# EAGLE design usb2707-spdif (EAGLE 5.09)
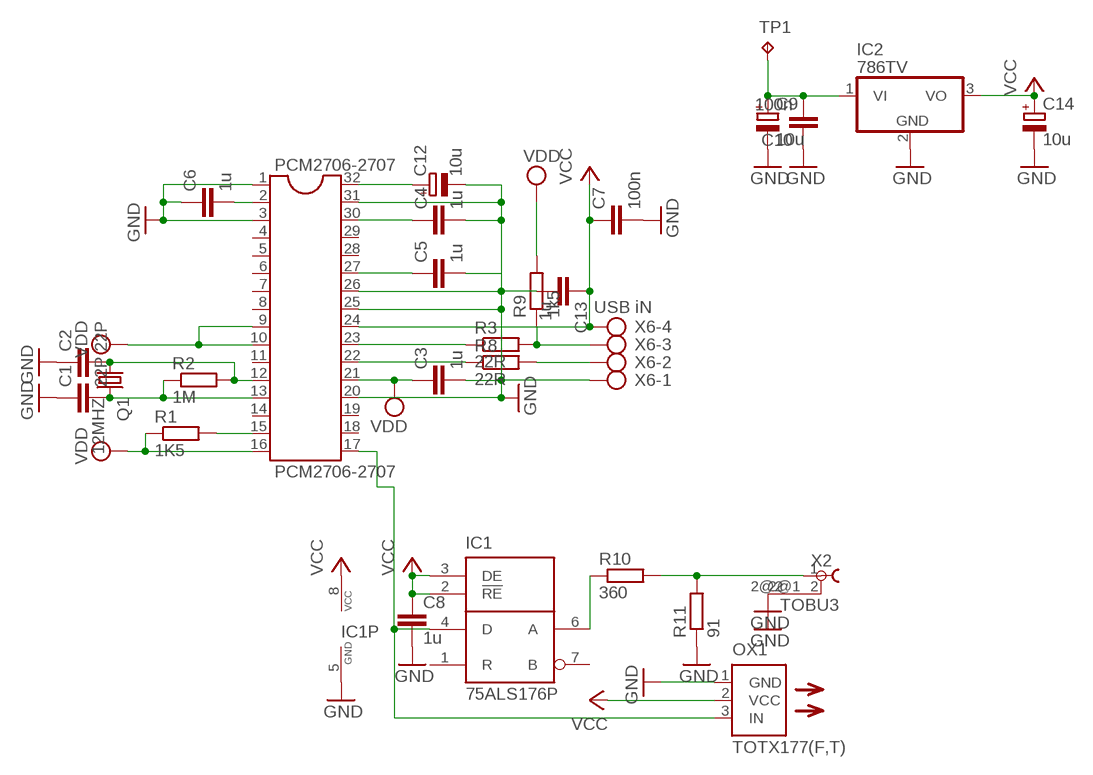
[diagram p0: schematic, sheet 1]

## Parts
C1  22P  C5/2.5  [C5B2.5]
C2  22P  C5/2.5  [C5B2.5]
C3  1u  C5/2.5  [C5B2.5]
C4  1u  C5/2.5  [C5B2.5]
C5  1u  C5/2.5  [C5B2.5]
C6  1u  C5/2.5  [C5B2.5]
C7  100n  C5/2.5  [C5B2.5]
C8  1u  C5/2.5  [C5B2.5]
C9  10u  CPOL-EUE5-5  [E5-5]
C10  100n  C5/2.5  [C5B2.5]
C12  10u  CPOL-EUE5-5  [E5-5]
C13  1u  C5/2.5  [C5B2.5]
C14  10u  CPOL-EUE5-5  [E5-5]
IC1  75ALS176P  [DIL08]
IC2  786TV  [TO220V]
OX1  TOTX177(F,T)  [TOTX]
PCM2706-2707  PCM2706-2707  DIL32  [DIL32]
Q1  12MHZ  CRYSTALHC49U-V  [HC49U-V]
R1  1K5  R-EU_0207/10  [0207/10]
R2  1M  R-EU_0207/10  [0207/10]
R3  22R  R-EU_0207/10  [0207/10]
R8  22R  R-EU_0207/10  [0207/10]
R9  1k5  R-EU_0207/10  [0207/10]
R10  360  R-EU_0207/10  [0207/10]
R11  91  R-EU_0207/10  [0207/10]
TP1  TPPAD1-13Y  [P1-13Y]
X2  TOBU3  [TOBU3]
X6  USB iN  AK500/4  [AK500/4]

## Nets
GND: C1.1 C2.1 C3.2 C4.2 C5.2 C6.1 C7.2 C8.2 C9.- C10.1 C12.- C13.2 C14.- IC1.5(GND) IC2.2(GND) OX1.1(GND) PCM2706-2707.1 PCM2706-2707.3 PCM2706-2707.20 PCM2706-2707.25 PCM2706-2707.26 PCM2706-2707.31 R11.1 X2.2@2 X6.1
N$1: C6.2 PCM2706-2707.2
N$2: C5.1 PCM2706-2707.27
N$3: C4.1 PCM2706-2707.30
N$4: C12.+ PCM2706-2707.32
N$5: R3.2 R9.1 X6.3
N$6: PCM2706-2707.15 R1.2
N$7: C9.+ C10.2 IC2.1(VI) TP1.TP
N$8: C2.2 PCM2706-2707.12 Q1.1 R2.2
N$9: C1.2 PCM2706-2707.13 Q1.2 R2.1
N$19: PCM2706-2707.23 R3.1
N$20: PCM2706-2707.22 R8.1
N$21: IC1.4(D) OX1.3(IN) PCM2706-2707.17
N$22: R8.2 X6.2
N$23: R10.2 R11.2 X2.1
N$30: IC1.6(A) R10.1
VCC: C7.1 C8.1 C13.1 C14.+ IC1.2(!RE) IC1.3(DE) IC1.8(VCC) IC2.3(VO) OX1.2(VCC) PCM2706-2707.24 X6.4
VDD: C3.1 PCM2706-2707.9 PCM2706-2707.10 PCM2706-2707.16 PCM2706-2707.21 R1.1 R9.2
Unconnected: IC1.1(R) IC1.7(B) PCM2706-2707.4 PCM2706-2707.5 PCM2706-2707.6 PCM2706-2707.7 PCM2706-2707.8 PCM2706-2707.11 PCM2706-2707.14 PCM2706-2707.18 PCM2706-2707.19 PCM2706-2707.28 PCM2706-2707.29 X2.2 X2.2@1

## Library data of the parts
C1-C8 C10 C13 = capacitor-wima:C: CAPACITOR
C9 C12 C14 = rcl:CPOL-EU: POLARIZED CAPACITOR, European symbol
IC1 = texas:75ALS176: DIFFERENTIAL BUS TRANSCEIVERS TIA/EIA-422-B, TIA/EIA-422-B + TIA/EIA-422-B TIA/EIA-422-B Operate at Data Rates up to 35 Mbaud Source: http://focus.ti.com/lit/ds/symlink/sn65als176.pdf
IC2 = linear:78*: Positive VOLTAGE REGULATOR Source: http://cache.national.com/ds/LM/LM78L05.pdf http://www.fairchildsemi.com/ds/LM/LM7805.pdf
OX1 = pavouk:TOTX177(F,T): FIBER OPTIC TRANSMITTING MODULE
PCM2706-2707 = ic-package:DIL32: Dual In Line
Q1 = crystal:CRYSTAL: CRYSTAL
R1-R3 R8-R11 = rcl:R-EU_: RESISTOR, European symbol
TP1 = testpad:TP: Test pad
X2 = con-hirschmann:TOBU3: Female Cinch CONNECTOR ( RCA Jack )
X6 = con-ptr500:AK500/4: CONNECTOR

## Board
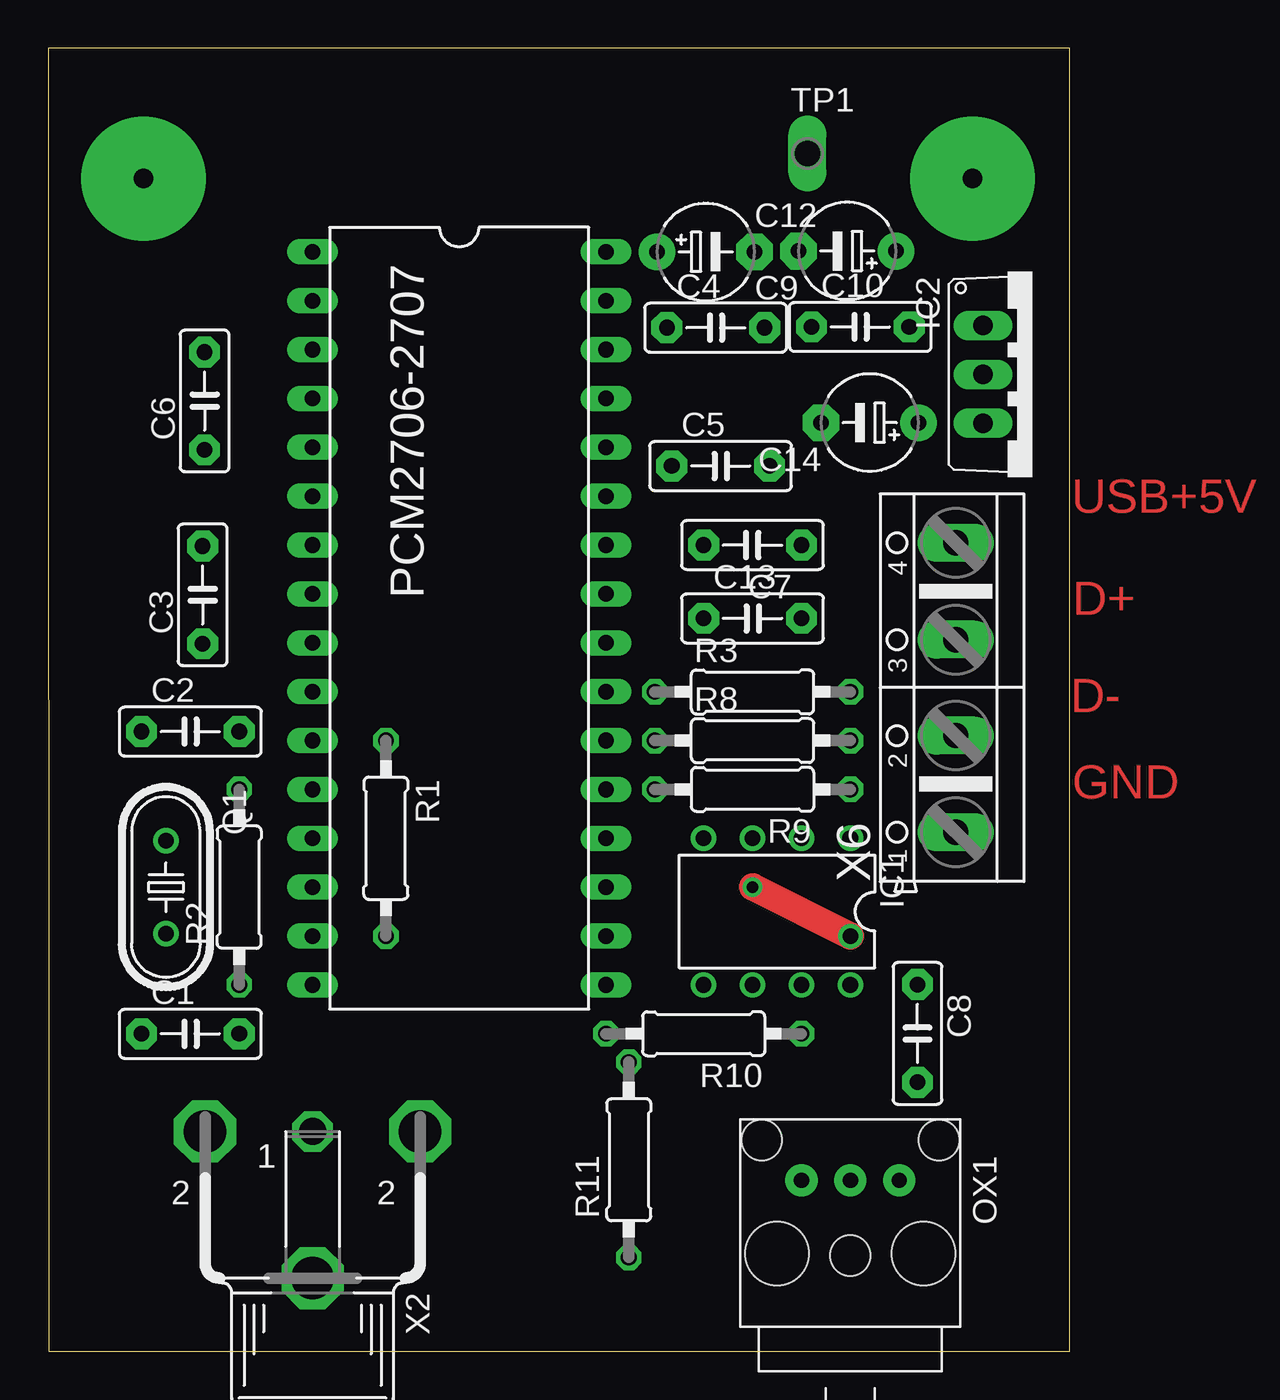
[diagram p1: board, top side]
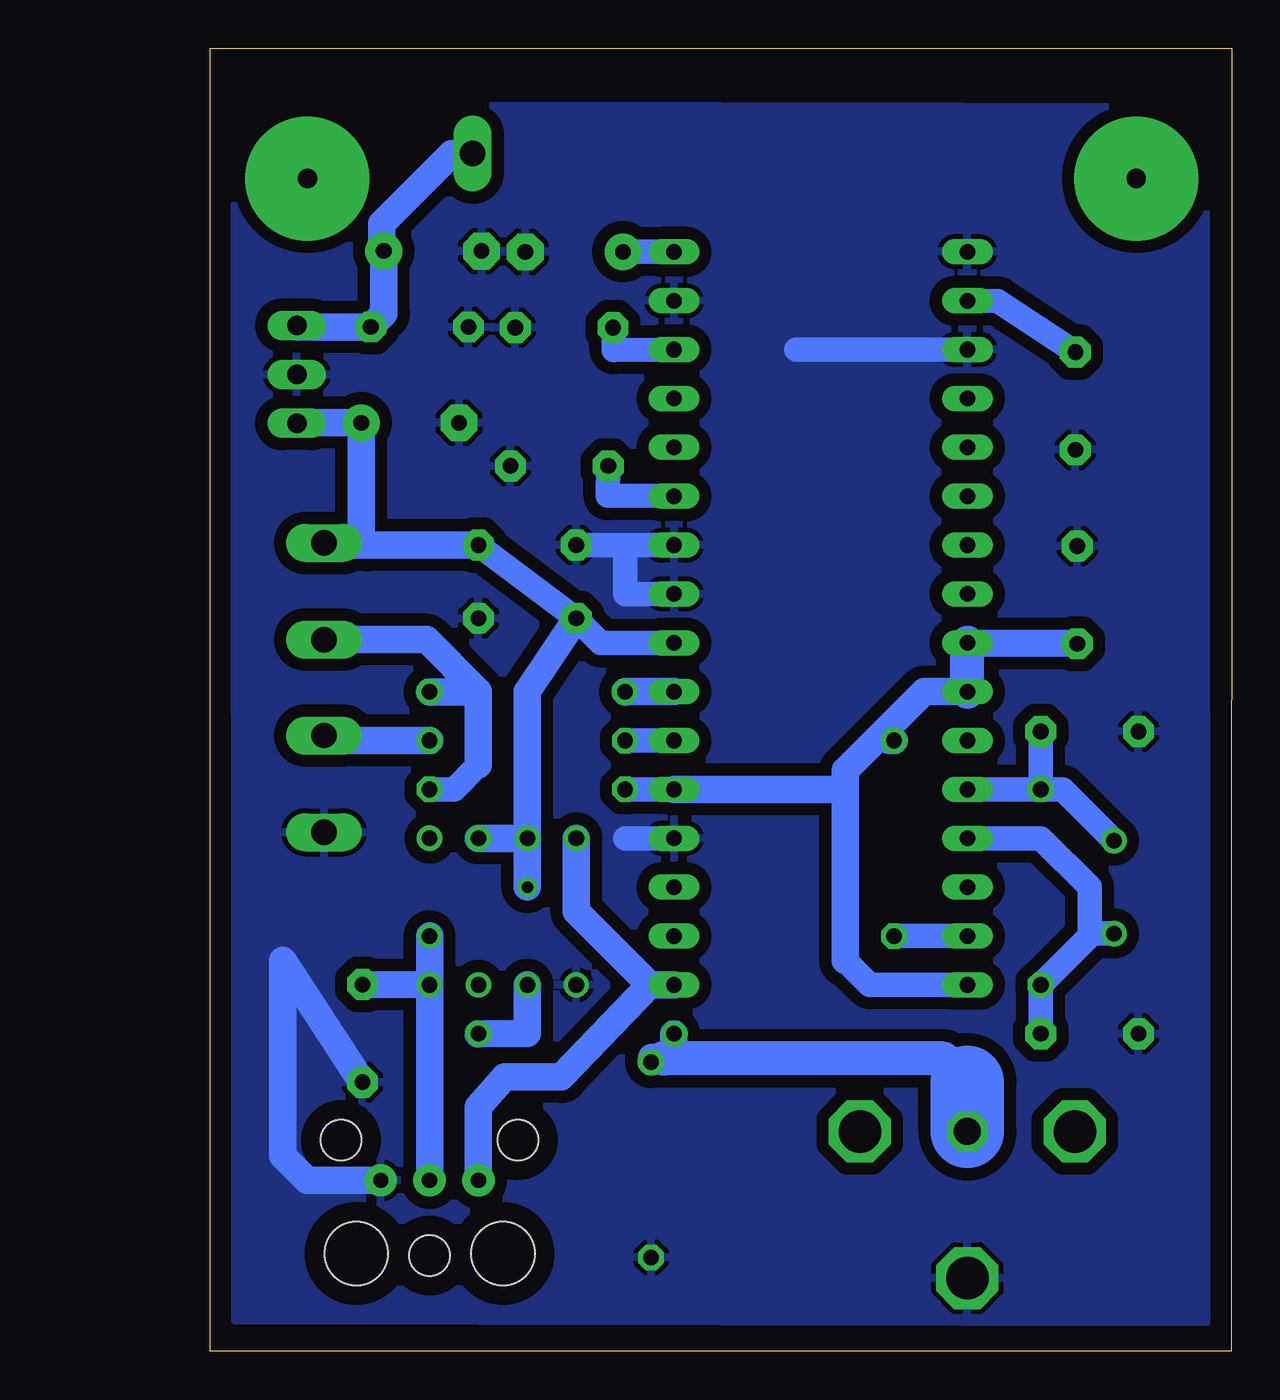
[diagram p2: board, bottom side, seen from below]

Size 53.09 x 67.74 mm. Coordinates in mm from the lower left corner, seen from the top.
Outline: 0.02,0 53.09,0 53.07,67.74 0,67.74 0.02,0
Copper layers (1*16): Top 0.035mm / dielectric 1.5mm / Bottom 0.035mm
Design rules "default *": minimum track width 10mil, minimum drill 24mil, track to track 25mil, track to pad 25mil, pad to pad 25mil, via to via 25mil, smd to smd 8mil, copper to edge 40mil, drill to drill 8mil, minimum pad ring 10mil, minimum via ring 8mil, stop-mask expansion 4mil, vias tented up to drill 0mil, thermal gap 10mil

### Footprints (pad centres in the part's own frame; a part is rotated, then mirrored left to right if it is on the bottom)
C5B2.5 = drill 0.813 pad 1.6 octagon: 1 -2.54,0; 2 2.54,0
E5-5 = drill 0.813 pad 1.905 round: + -2.54,0 | drill 0.813 pad 1.905 octagon: - 2.54,0
DIL08 = drill 0.813 pad 1.27 round: 1 -3.81,-3.81; 2 -1.27,-3.81; 3 1.27,-3.81; 4 3.81,-3.81; 5 3.81,3.81; 6 1.27,3.81; 7 -1.27,3.81; 8 -3.81,3.81
TO220V = drill 1.016 long: 1 -2.54,-2.54; 2 0,-2.54; 3 2.54,-2.54
TOTX = drill 0.8 pad 1.676 round: 1 -3.81,2.54; 2 -3.81,0; 3 -3.81,-2.54 | hole 3.3: 0,-3.81; 0,3.81 | hole 2.1: 0.09,0; -5.91,4.6; -5.91,-4.6
DIL32 = drill 0.813 long: 1 -19.05,-7.62; 2 -16.51,-7.62; 3 -13.97,-7.62; 4 -11.43,-7.62; 5 -8.89,-7.62; 6 -6.35,-7.62; 7 -3.81,-7.62; 8 -1.27,-7.62; 9 1.27,-7.62; 10 3.81,-7.62; 11 6.35,-7.62; 12 8.89,-7.62; 13 11.43,-7.62; 14 13.97,-7.62; 15 16.51,-7.62; 16 19.05,-7.62; 17 19.05,7.62; 18 16.51,7.62; 19 13.97,7.62; 20 11.43,7.62; 21 8.89,7.62; 22 6.35,7.62; 23 3.81,7.62; 24 1.27,7.62; 25 -1.27,7.62; 26 -3.81,7.62; 27 -6.35,7.62; 28 -8.89,7.62; 29 -11.43,7.62; 30 -13.97,7.62; 31 -16.51,7.62; 32 -19.05,7.62
HC49U-V = drill 0.813 round: 1 -2.413,0; 2 2.413,0
0207/10 = drill 0.813 octagon: 1 -5.08,0; 2 5.08,0
P1-13Y = drill 1.321 pad 1.905 long: TP 0,0
TOBU3 = drill 1.397 octagon: 1 0,-2.54 | drill 2.21 octagon: 2 5.588,-2.54; 2@1 -5.588,-2.54; 2@2 0,5.08
AK500/4 = drill 1.321 long: 1 -7.518,0; 2 -2.489,0; 3 2.489,0; 4 7.518,0

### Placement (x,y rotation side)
C1  7.39,16.51 0 top
C2  7.39,32.22 0 top
C3  8.03,39.32 90 top
C4  34.69,53.21 0 top
C5  34.94,46.02 0 top
C6  8.13,49.4 90 top
C7  36.6,41.91 180 top
C8  45.17,16.53 270 top
C9  41.52,57.19 180 top
C10  42.2,53.25 0 top
C12  34.17,57.15 0 top
C13  36.6,38.1 0 top
C14  42.69,48.27 180 top
IC1  37.87,22.86 180 top
IC2  51.12,50.78 270 top
OX1  41.68,5.08 270 top
PCM2706-2707  21.36,38.1 270 top
Q1  6.12,24.13 270 top
R1  17.55,26.67 270 top
R2  9.93,24.13 90 top
R3  36.6,34.28 0 top
R8  36.6,31.75 0 top
R9  36.6,29.21 180 top
R10  34.06,16.51 180 top
R11  30.17,9.96 90 top
TP1  39.45,62.26 0 top
X2  13.74,8.89 180 top
X6  47.16,34.5 90 top

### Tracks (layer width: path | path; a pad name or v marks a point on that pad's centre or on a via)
GND
  Bottom 1.27: 31.52,41.91 PCM2706-2707.26 | 31.52,41.91 31.52,39.37 PCM2706-2707.25 | PCM2706-2707.3 22.63,52.07 | 31.52,41.91 C7.2 | PCM2706-2707.20 31.52,26.67
  Bottom 1.422: OX1.1 48.03,8.89 49.3,10.16 49.3,20.32 C8.2
  pour Bottom: 1.34,64.68 51.84,64.77 51.8,1.61 1.3,1.52
N$1
  Bottom 1.27: PCM2706-2707.2 12.15,54.6 C6.2
N$2
  Bottom 1.27: C5.1 32.42,44.47 PCM2706-2707.27
N$3
  Bottom 1.27: PCM2706-2707.30 32.11,52.05 32.11,53.21 C4.1
N$4
  Bottom 1.27: PCM2706-2707.32 C12.+
N$5
  Bottom 1.27: 39.14,30.48 40.41,29.21 R9.1
  Bottom 1.422: X6.3 41.84,36.99 39.27,34.41 | 39.14,30.48 39.14,34.29 39.27,34.41 | R3.2 39.4,34.28 39.27,34.41
N$6
  Bottom 1.27: PCM2706-2707.15 R1.2
N$7
  Bottom 1.422: TP1.TP 40.52,62.26 44.17,58.61 44.17,57.3 C9.+ 44.06,53.93 C10.2 48.51,53.25 IC2.1
N$8
  Bottom 1.27: R2.2 PCM2706-2707.12 | Q1.1 8.79,29.21 R2.2 | R2.2 C2.2
N$9
  Bottom 1.27: PCM2706-2707.13 9.93,26.67 7.39,24.13 7.39,21.59 | 7.39,21.59 R2.1 C1.2 | Q1.2 7.26,21.72 7.39,21.59
N$12  (via drill 0.8 pad 2.18)
  other vias: 37.07,10.99
N$13  (via drill 0.8 pad 2.18)
  other vias: 46.28,11
N$14  (via drill 0.8 pad 2.18)
  other vias: 41.67,5
N$19
  Bottom 1.422: PCM2706-2707.23 R3.1
N$20
  Bottom 1.27: PCM2706-2707.22 R8.1
N$21
  Bottom 1.422: PCM2706-2707.17 30.25,19.05 | 30.25,19.05 34.83,14.26 37.78,14.26 39.14,12.7 OX1.3 | IC1.4 34.06,22.86 30.25,19.05
N$22
  Bottom 1.422: R8.2 46.9,31.75 X6.2
N$23
  Bottom 1.422: R11.2 30.15,15.27 30.15,15.25 29.55,15.25 29,15.25 29,16.51 R10.2
  Bottom 1.778: 13.74,13.99 14.97,15.22 29.52,15.22 29.55,15.25
  Bottom 3.81: X2.1 13.74,13.99
N$26  (via drill 1 pad 6.45)
  other vias: 4.96,60.96
N$29  (via drill 1 pad 6.45)
  other vias: 48.03,60.96
N$30
  Bottom 1.422: IC1.6 36.61,16.53 R10.1
VCC  (via drill 0.6, 0.8 pad 1.27)
  Top 1.422: v41.68,21.59 v36.6,24.13
  Bottom 1.27: C7.1 C13.1 32.79,36.83 PCM2706-2707.24
  Bottom 1.422: OX1.2 IC1.8 | IC1.3 36.6,34.29 C13.1 | v36.6,24.13 IC1.3 | IC1.3 IC1.2 | IC1.8 C8.1 | IC1.8 v41.68,21.59 | C7.1 44.94,41.91 | 44.94,41.91 47.16,41.91 X6.4 | IC2.3 48.55,48.27 C14.+ 45.23,42.2 44.94,41.91
VDD
  Bottom 1.27: PCM2706-2707.21 R9.2 | 20.09,20.32 18.82,19.05 PCM2706-2707.16
  Bottom 1.422: PCM2706-2707.9 C3.1 | 20.09,20.32 20.09,29.21 | 20.09,29.21 20.09,30.19 18.16,32.12 | 20.09,29.21 PCM2706-2707.21 | PCM2706-2707.10 15.99,34.29 18.16,32.12 | R1.1 17.79,31.75 18.16,32.12
  Bottom 1.778: PCM2706-2707.10 PCM2706-2707.9

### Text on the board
Top: USB+5V | D+ | D- | GND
